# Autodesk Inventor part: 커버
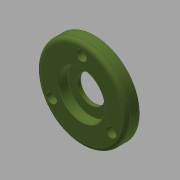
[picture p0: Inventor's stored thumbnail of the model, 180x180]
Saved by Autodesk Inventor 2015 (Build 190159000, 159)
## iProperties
Created: 2016-06
Part Number: 커버
Material: 알루미늄 6061
Document SubType Name: Modeling
Designer: mduedu
Density: 2.71 g/cm^3
Appearance: 올리브 녹색
Author: mduedu
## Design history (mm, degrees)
sketch "스케치1"
  geometry: C1 r 34 at (0, 0); 1 further point
  constraints: 1 centre point, 1 coincident
  dimensions: "d0" = 68 diameter of C1
extrude "돌출1" new body sketch "스케치1" distance "d2" = 10; taper "d3" = 0 deg
sketch "스케치2"
  geometry: C1 r 21 at (0, 0); 1 further point
  constraints: 1 centre point, 1 coincident
  dimensions: "d4" = 42 diameter of C1
extrude "돌출2" join sketch "스케치2" distance "d6" = 3; taper "d7" = 0 deg
fillet "모깎기1" dims "d8" = 3
hole "구멍1" diameter "d11" = 35; stored, may be unused: countersink angle "d15" = 90 deg, drill point angle "d17" = 0 deg; dims "d9" = 10, "d10" = 10, "d12" = 6, "d13" = 4, "d14" = 2, "d16" = 3
hole "구멍2" diameter "d20" = 35; stored, may be unused: countersink angle "d24" = 90 deg, drill point angle "d26" = 0 deg; dims "d21" = 6, "d22" = 4, "d23" = 2, "d25" = 7.3, "d73" = 10, "d74" = 10
hole "구멍3" diameter "d29" = 21; stored, may be unused: countersink angle "d33" = 90 deg, drill point angle "d35" = 0 deg; dims "d27" = 10, "d28" = 10, "d30" = 6, "d31" = 4, "d32" = 2, "d34" = 5
fillet "모깎기2" dims "d36" = 3
fillet "모깎기3" dims "d37" = 0.1
chamfer "모따기1" distance "d38" = 0.7; stored, may be unused: second distance "d39" = 2, angle "d40" = 30 deg
chamfer "모따기2" distance "d42" = 0.5; stored, may be unused: second distance "d43" = 2, angle "d44" = 30 deg
sketch "스케치5" dims "d60" = 52
  geometry: 3 further points
  constraints: 2 vertical alignment, 1 coincident, 2 other
hole "구멍5" sketch "스케치5" at (0, 26) diameter "d61" = 4.5; stored, may be unused: countersink angle "d65" = 90 deg, drill point angle "d67" = 118 deg; dims "d62" = 6, "d63" = 8, "d64" = 4.6, "d66" = 8
node "솔리드1"
pattern_circular "원형 패턴1" dims angle "d69" = 360 deg
